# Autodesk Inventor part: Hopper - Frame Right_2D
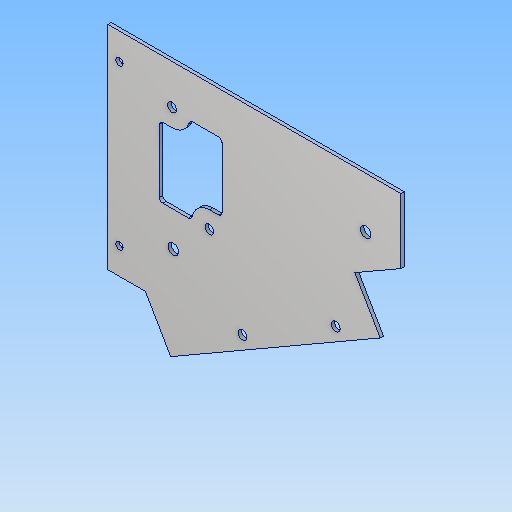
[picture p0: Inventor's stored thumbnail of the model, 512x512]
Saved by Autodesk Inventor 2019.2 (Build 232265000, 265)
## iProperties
Created: 2019-02
Part Number: Hopper - Frame Right_2D
Material: Aluminum 6061
Document SubType Name: Modeling
Designer: User
Density: 2.7 g/cm^3
Appearance: Aluminum - Flat
Author: User
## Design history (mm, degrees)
sketch "er - Frame Right sketch"
  geometry: L1 (0.646, 95.131)-(-3.799, 95.131); L2 (-5.387, 93.544)-(-5.387, 63.242); L3 (-3.799, 61.654)-(8.531, 61.654); L4 (10.01, 62.663)-(10.901, 64.939); L5 (18.499, 70.122)-(22.961, 70.122); L6 (24.549, 71.71)-(24.549, 100.88); L7 (22.961, 102.468)-(10.391, 102.468); L8 (8.913, 101.459)-(8.545, 100.521); L9 (100.173, 57.835)-(0, 0); L10 (0, 0)-(-12.114, 20.982); L11 (-12.114, 20.982)-(-30.059, 20.982); L12 (-30.059, 20.982)-(-30.059, 122.582); L13 (-30.059, 122.582)-(110.056, 122.582); L14 (110.056, 122.582)-(110.056, 91.518); L15 (110.056, 91.518)-(88.059, 78.818); L16 (88.059, 78.818)-(100.173, 57.835); C1 r 2.54 at (1.228, 45.149); C2 r 2.54 at (93.286, 98.298); C3 r 2.134 at (0.646, 103.615); C4 r 2.134 at (18.499, 61.963); C5 r 2.159 at (34.314, 26.227); C6 r 2.159 at (78.909, 51.974); C7 r 1.778 at (-24.503, 33.682); C8 r 1.778 at (-24.503, 109.882); A1 r 1.588 centre (-3.799, 93.544) between (-3.799, 95.131) and (-5.387, 93.544); A2 r 1.587 centre (-3.799, 63.242) between (-5.387, 63.242) and (-3.799, 61.654); A3 r 1.587 centre (8.531, 63.242) between (8.531, 61.654) and (10.01, 62.663); A4 r 8.16 centre (18.499, 61.963) between (18.499, 70.122) and (10.901, 64.939); A5 r 1.588 centre (22.961, 71.71) between (22.961, 70.122) and (24.549, 71.71); A6 r 1.588 centre (22.961, 100.88) between (24.549, 100.88) and (22.961, 102.468); A7 r 1.588 centre (10.391, 100.88) between (10.391, 102.468) and (8.913, 101.459); A8 r 8.484 centre (0.646, 103.615) between (0.646, 95.131) and (8.545, 100.521)
  constraints: 32 end point, 16 centre point, 16 point on circle
extrude "er - Frame Right extrude" new body sketch "er - Frame Right sketch" stored distance "d0" = 1.5875; taper "d1" = 0 deg
node "er - Frame Right"
